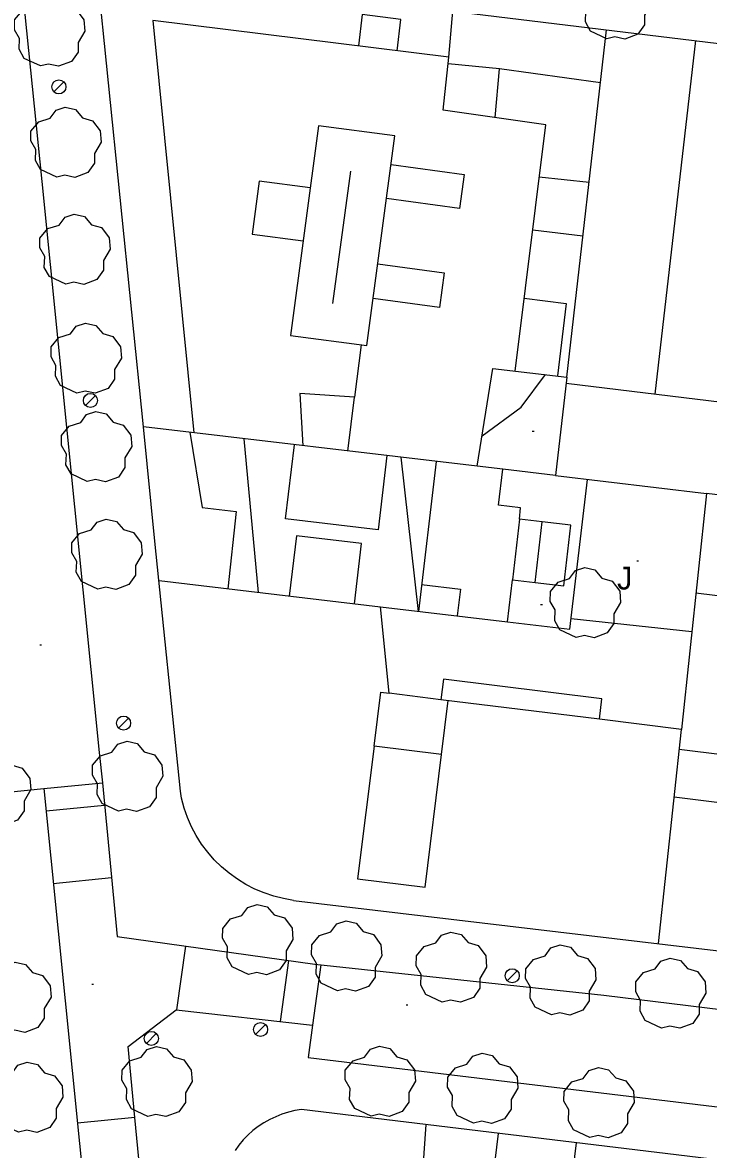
# Model space of a CAD drawing. Extents: x 431390 to 432653, y 4586754 to 4589600.
# Drawn here: x 431849.6 to 431888.6, y 4587029.7 to 4587093.8 of the extents above; entities that cross this region are included whole.
import ezdxf

# ---------------------------------------------------------------- set-up
doc = ezdxf.new("R2010")
doc.units = 0
for name, color, linetype in [('COM_17LS_LN', 7, 'Continuous'), ('COM_51_LN', 7, 'Continuous'), ('CON_01_LN', 7, 'Continuous'), ('CON_01FI_LN', 7, 'Continuous'), ('CON_03_LN', 7, 'Continuous'), ('CON_04_LN', 7, 'Continuous'), ('CON_07_LN', 7, 'Continuous'), ('CON_16_LN', 7, 'Continuous'), ('CON_29_LN', 7, 'Continuous'), ('ENE_06_PT', 7, 'Continuous'), ('ORO_03_PT', 7, 'Continuous'), ('TOP_15JA_TX', 7, 'Continuous'), ('VEG_03_PT', 7, 'Continuous'), ('VEG_06_LN', 7, 'Continuous')]:
    doc.layers.add(name, color=color, linetype=linetype)

msp = doc.modelspace()

# ---------------------------------------------------------------- linework, layer by layer
at = {"layer": 'COM_17LS_LN'}
for points in [[(431837.008, 4587166.5), (431842.053, 4587116.407), (431848.565, 4587051.747), (431848.738, 4587050.028), (431850.776, 4587050.233)], [(431849.159, 4587099.733), (431850.662, 4587084.802), (431853.937, 4587052.287), (431854.11, 4587050.568), (431854.957, 4587041.808), (431866.203, 4587040.244), (431882.634, 4587038.474), (431909.565, 4587035.179)], [(431850.776, 4587050.233), (431854.11, 4587050.568)], [(431850.776, 4587050.233), (431853.209, 4587026.07)], [(431866.538, 4587040.208), (431866.058, 4587036.756)], [(431855.957, 4587031.509), (431855.571, 4587035.553), (431858.31, 4587037.64), (431866.058, 4587036.756)], [(431866.058, 4587036.756), (431865.809, 4587034.924)], [(431865.809, 4587034.924), (431908.896, 4587029.72), (431931.717, 4587026.927), (431949.6, 4587024.752)], [(431860.702, 4586984.127), (431856.446, 4587026.396), (431855.957, 4587031.509)]]:
    msp.add_lwpolyline(points, dxfattribs=at)
at = {"layer": 'COM_51_LN'}
for points in [[(431854.236, 4587049.261), (431850.906, 4587048.94)], [(431851.32, 4587044.829), (431854.633, 4587045.163)], [(431858.841, 4587041.268), (431858.336, 4587037.637)], [(431864.702, 4587040.453), (431864.217, 4587036.966)], [(431855.957, 4587031.508), (431852.693, 4587031.193)]]:
    msp.add_lwpolyline(points, dxfattribs=at)
at = {"layer": 'CON_01_LN'}
for points in [[(431856.444, 4587070.829), (431853.79, 4587096.96), (431873.881, 4587094.519), (431904.331, 4587090.82)], [(431864.98, 4587043.87), (431864.415, 4587043.968), (431863.86, 4587044.108), (431863.316, 4587044.29), (431862.788, 4587044.513), (431862.278, 4587044.775), (431861.79, 4587045.075), (431861.325, 4587045.41), (431860.888, 4587045.78), (431860.479, 4587046.182), (431860.102, 4587046.614), (431859.759, 4587047.073), (431859.451, 4587047.556), (431859.181, 4587048.062), (431858.95, 4587048.586), (431858.759, 4587049.127), (431858.61, 4587049.68), (431858.55, 4587050.09), (431857.104, 4587064.328), (431856.444, 4587070.829)], [(431864.98, 4587043.87), (431902.943, 4587039.364), (431950.282, 4587033.571)], [(431903.511, 4587027.351), (431865.44, 4587031.96), (431865.064, 4587031.898), (431864.693, 4587031.809), (431864.329, 4587031.695), (431863.974, 4587031.555), (431863.63, 4587031.39), (431863.299, 4587031.202), (431862.981, 4587030.991), (431862.679, 4587030.759), (431862.394, 4587030.505), (431862.128, 4587030.232), (431861.881, 4587029.941), (431861.656, 4587029.634)]]:
    msp.add_lwpolyline(points, dxfattribs=at)
at = {"layer": 'CON_01FI_LN'}
msp.add_lwpolyline([(431873.372, 4587055.294), (431870.42, 4587055.66), (431869.927, 4587060.58), (431877.157, 4587059.724), (431877.44, 4587062.118), (431878.728, 4587061.966), (431879.137, 4587065.422), (431877.846, 4587065.575), (431877.891, 4587066.223), (431876.648, 4587066.37), (431876.889, 4587068.409), (431875.432, 4587068.581), (431876.33, 4587074.14), (431880.533, 4587073.662), (431879.893, 4587068.053), (431888.48, 4587067.037), (431887.048, 4587053.601), (431882.387, 4587054.178), (431882.531, 4587055.341), (431873.516, 4587056.457), (431873.372, 4587055.294)], dxfattribs=at)
at = {"layer": 'CON_03_LN'}
for points in [[(431880.533, 4587073.662), (431882.789, 4587093.437)], [(431875.432, 4587068.581), (431856.444, 4587070.829)], [(431896.142, 4587066.129), (431888.48, 4587067.037)], [(431857.333, 4587062.071), (431869.927, 4587060.58)], [(431885.748, 4587041.405), (431887.048, 4587053.601)]]:
    msp.add_lwpolyline(points, dxfattribs=at)
at = {"layer": 'CON_04_LN'}
for points in [[(431873.83, 4587091.87), (431874.052, 4587094.498)], [(431877.602, 4587073.995), (431879.33, 4587088.03), (431873.49, 4587088.85), (431873.83, 4587091.87), (431856.98, 4587093.97), (431859.306, 4587070.49)], [(431870.873, 4587092.239), (431871.095, 4587094.022), (431868.899, 4587094.296), (431868.677, 4587092.512)], [(431876.447, 4587088.435), (431876.7, 4587091.21), (431873.788, 4587091.499)], [(431882.444, 4587090.409), (431876.7, 4587091.21)], [(431869.15, 4587075.45), (431870.75, 4587087.39), (431866.413, 4587087.971), (431864.813, 4587076.031), (431869.15, 4587075.45)], [(431870.532, 4587085.76), (431874.692, 4587085.202), (431874.432, 4587083.265), (431870.272, 4587083.823)], [(431878.965, 4587085.067), (431881.799, 4587084.757)], [(431865.938, 4587084.426), (431863.028, 4587084.816), (431862.624, 4587081.799), (431865.534, 4587081.409)], [(431881.448, 4587081.68), (431878.591, 4587082.031)], [(431869.774, 4587080.107), (431873.56, 4587079.6), (431873.296, 4587077.627), (431869.51, 4587078.134)], [(431878.113, 4587078.145), (431880.503, 4587077.851), (431879.995, 4587073.723)], [(431868.079, 4587069.452), (431868.46, 4587072.52), (431865.34, 4587072.72), (431865.518, 4587069.755)], [(431901.2, 4587070.77), (431880.492, 4587073.299)], [(431859.092, 4587070.516), (431859.78, 4587066.24), (431861.73, 4587066), (431861.243, 4587061.608)], [(431862.156, 4587070.153), (431862.971, 4587061.404)], [(431870.301, 4587069.188), (431869.8, 4587064.96), (431864.534, 4587065.583), (431865.035, 4587069.812)], [(431873.097, 4587068.857), (431872.086, 4587060.324), (431871.101, 4587069.094)], [(431877.846, 4587065.575), (431877.44, 4587062.118)], [(431868.448, 4587060.755), (431868.855, 4587064.192), (431865.15, 4587064.631), (431864.743, 4587061.194)], [(431872.266, 4587061.844), (431874.477, 4587061.582), (431874.297, 4587060.063)], [(431895.447, 4587060.426), (431887.874, 4587061.349)], [(431869.573, 4587052.646), (431869.956, 4587055.718), (431870.42, 4587055.66)], [(431882.387, 4587054.178), (431873.372, 4587055.294)], [(431873.406, 4587052.169), (431873.788, 4587055.243)], [(431872.468, 4587044.619), (431873.406, 4587052.169), (431869.573, 4587052.646), (431868.634, 4587045.096), (431872.468, 4587044.619)], [(431886.928, 4587052.471), (431891.972, 4587051.856), (431891.639, 4587049.126), (431886.636, 4587049.736)], [(431871.676, 4587018.848), (431872.526, 4587031.102)], [(431881.065, 4587030.068), (431880.688, 4587026.952), (431876.266, 4587027.487), (431876.643, 4587030.604)]]:
    msp.add_lwpolyline(points, dxfattribs=at)
at = {"layer": 'CON_07_LN'}
for points in [[(431875.711, 4587070.309), (431877.94, 4587071.95), (431879.327, 4587073.799)], [(431878.728, 4587061.966), (431880.358, 4587061.773), (431880.767, 4587065.229), (431879.137, 4587065.422)]]:
    msp.add_lwpolyline(points, dxfattribs=at)
at = {"layer": 'CON_16_LN'}
for points in [[(431879.893, 4587068.053), (431876.889, 4587068.409)], [(431877.157, 4587059.724), (431880.708, 4587059.304), (431881.718, 4587067.837)]]:
    msp.add_lwpolyline(points, dxfattribs=at)
at = {"layer": 'CON_29_LN'}
for points in [[(431887.858, 4587092.821), (431885.536, 4587072.683)], [(431868.221, 4587085.388), (431867.212, 4587077.858)], [(431868.837, 4587075.492), (431868.46, 4587072.52)]]:
    msp.add_lwpolyline(points, dxfattribs=at)
at = {"layer": 'ENE_06_PT'}
for p, q in [((431851.922, 4587090.462), (431851.356, 4587089.896)), ((431853.712, 4587072.612), (431853.146, 4587072.046)), ((431855.602, 4587054.242), (431855.036, 4587053.676)), ((431877.712, 4587039.862), (431877.146, 4587039.296)), ((431863.392, 4587036.802), (431862.826, 4587036.236)), ((431857.179, 4587036.29), (431856.613, 4587035.724))]:
    msp.add_line(p, q, dxfattribs=at)
for centre in [(431851.639, 4587090.179), (431853.429, 4587072.329), (431855.319, 4587053.959), (431877.429, 4587039.579), (431863.109, 4587036.519), (431856.896, 4587036.007)]:
    msp.add_circle(centre, 0.4, dxfattribs=at)
at = {"layer": 'ORO_03_PT'}
for p, q in [((431878.57, 4587070.58), (431878.67, 4587070.58)), ((431884.51, 4587063.19), (431884.61, 4587063.19)), ((431879.04, 4587060.72), (431879.14, 4587060.72)), ((431850.556, 4587058.424), (431850.656, 4587058.424)), ((431853.511, 4587039.094), (431853.611, 4587039.094)), ((431871.388, 4587037.92), (431871.488, 4587037.92))]:
    msp.add_line(p, q, dxfattribs=at)
at = {"layer": 'VEG_03_PT'}
for points in [[(431882.804, 4587092.921), (431881.877, 4587093.356), (431881.589, 4587093.877), (431881.612, 4587094.491), (431881.33, 4587094.983), (431881.338, 4587095.546), (431881.779, 4587096.081), (431882.432, 4587096.285), (431882.767, 4587096.736), (431883.293, 4587096.906), (431883.873, 4587096.773), (431884.273, 4587096.307), (431884.847, 4587096.137), (431885.281, 4587095.554), (431885.33, 4587094.912), (431884.947, 4587094.265), (431884.947, 4587093.715), (431884.575, 4587093.181), (431883.836, 4587092.906), (431883.271, 4587093.034), (431882.804, 4587092.921)], [(431850.584, 4587091.371), (431849.657, 4587091.806), (431849.369, 4587092.327), (431849.392, 4587092.941), (431849.11, 4587093.433), (431849.118, 4587093.996), (431849.559, 4587094.531), (431850.212, 4587094.735), (431850.547, 4587095.186), (431851.073, 4587095.356), (431851.653, 4587095.223), (431852.053, 4587094.757), (431852.627, 4587094.587), (431853.061, 4587094.004), (431853.11, 4587093.362), (431852.727, 4587092.715), (431852.727, 4587092.165), (431852.355, 4587091.631), (431851.616, 4587091.356), (431851.051, 4587091.484), (431850.584, 4587091.371)], [(431851.514, 4587085.041), (431850.587, 4587085.476), (431850.299, 4587085.997), (431850.322, 4587086.611), (431850.04, 4587087.103), (431850.048, 4587087.666), (431850.489, 4587088.201), (431851.142, 4587088.405), (431851.477, 4587088.856), (431852.003, 4587089.026), (431852.583, 4587088.893), (431852.983, 4587088.427), (431853.557, 4587088.257), (431853.991, 4587087.674), (431854.04, 4587087.032), (431853.657, 4587086.385), (431853.657, 4587085.835), (431853.285, 4587085.301), (431852.546, 4587085.026), (431851.981, 4587085.154), (431851.514, 4587085.041)], [(431852.024, 4587078.951), (431851.097, 4587079.386), (431850.809, 4587079.907), (431850.832, 4587080.521), (431850.55, 4587081.013), (431850.558, 4587081.576), (431850.999, 4587082.111), (431851.652, 4587082.315), (431851.987, 4587082.766), (431852.513, 4587082.936), (431853.093, 4587082.803), (431853.493, 4587082.337), (431854.067, 4587082.167), (431854.501, 4587081.584), (431854.55, 4587080.942), (431854.167, 4587080.295), (431854.167, 4587079.745), (431853.795, 4587079.211), (431853.056, 4587078.936), (431852.491, 4587079.064), (431852.024, 4587078.951)], [(431852.664, 4587072.751), (431851.737, 4587073.186), (431851.449, 4587073.707), (431851.472, 4587074.321), (431851.19, 4587074.813), (431851.198, 4587075.376), (431851.639, 4587075.911), (431852.292, 4587076.115), (431852.627, 4587076.566), (431853.153, 4587076.736), (431853.733, 4587076.603), (431854.133, 4587076.137), (431854.707, 4587075.967), (431855.141, 4587075.384), (431855.19, 4587074.742), (431854.807, 4587074.095), (431854.807, 4587073.545), (431854.435, 4587073.011), (431853.696, 4587072.736), (431853.131, 4587072.864), (431852.664, 4587072.751)], [(431853.254, 4587067.711), (431852.327, 4587068.146), (431852.039, 4587068.667), (431852.062, 4587069.281), (431851.78, 4587069.773), (431851.788, 4587070.336), (431852.229, 4587070.871), (431852.882, 4587071.075), (431853.217, 4587071.526), (431853.743, 4587071.696), (431854.323, 4587071.563), (431854.723, 4587071.097), (431855.297, 4587070.927), (431855.731, 4587070.344), (431855.78, 4587069.702), (431855.397, 4587069.055), (431855.397, 4587068.505), (431855.025, 4587067.971), (431854.286, 4587067.696), (431853.721, 4587067.824), (431853.254, 4587067.711)], [(431853.844, 4587061.591), (431852.917, 4587062.026), (431852.629, 4587062.547), (431852.652, 4587063.161), (431852.37, 4587063.653), (431852.378, 4587064.216), (431852.819, 4587064.751), (431853.472, 4587064.955), (431853.807, 4587065.406), (431854.333, 4587065.576), (431854.913, 4587065.443), (431855.313, 4587064.977), (431855.887, 4587064.807), (431856.321, 4587064.224), (431856.37, 4587063.582), (431855.987, 4587062.935), (431855.987, 4587062.385), (431855.615, 4587061.851), (431854.876, 4587061.576), (431854.311, 4587061.704), (431853.844, 4587061.591)], [(431881.064, 4587058.831), (431880.137, 4587059.266), (431879.849, 4587059.787), (431879.872, 4587060.401), (431879.59, 4587060.893), (431879.598, 4587061.456), (431880.039, 4587061.991), (431880.692, 4587062.195), (431881.027, 4587062.646), (431881.553, 4587062.816), (431882.133, 4587062.683), (431882.533, 4587062.217), (431883.107, 4587062.047), (431883.541, 4587061.464), (431883.59, 4587060.822), (431883.207, 4587060.175), (431883.207, 4587059.625), (431882.835, 4587059.091), (431882.096, 4587058.816), (431881.531, 4587058.944), (431881.064, 4587058.831)], [(431855.024, 4587048.941), (431854.097, 4587049.376), (431853.809, 4587049.897), (431853.832, 4587050.511), (431853.55, 4587051.003), (431853.558, 4587051.566), (431853.999, 4587052.101), (431854.652, 4587052.305), (431854.987, 4587052.756), (431855.513, 4587052.926), (431856.093, 4587052.793), (431856.493, 4587052.327), (431857.067, 4587052.157), (431857.501, 4587051.574), (431857.55, 4587050.932), (431857.167, 4587050.285), (431857.167, 4587049.735), (431856.795, 4587049.201), (431856.056, 4587048.926), (431855.491, 4587049.054), (431855.024, 4587048.941)], [(431847.514, 4587048.181), (431846.587, 4587048.616), (431846.299, 4587049.137), (431846.322, 4587049.751), (431846.04, 4587050.243), (431846.048, 4587050.806), (431846.489, 4587051.341), (431847.142, 4587051.545), (431847.477, 4587051.996), (431848.003, 4587052.166), (431848.583, 4587052.033), (431848.983, 4587051.567), (431849.557, 4587051.397), (431849.991, 4587050.814), (431850.04, 4587050.172), (431849.657, 4587049.525), (431849.657, 4587048.975), (431849.285, 4587048.441), (431848.546, 4587048.166), (431847.981, 4587048.294), (431847.514, 4587048.181)], [(431862.424, 4587039.651), (431861.497, 4587040.086), (431861.209, 4587040.607), (431861.232, 4587041.221), (431860.95, 4587041.713), (431860.958, 4587042.276), (431861.399, 4587042.811), (431862.052, 4587043.015), (431862.387, 4587043.466), (431862.913, 4587043.636), (431863.493, 4587043.503), (431863.893, 4587043.037), (431864.467, 4587042.867), (431864.901, 4587042.284), (431864.95, 4587041.642), (431864.567, 4587040.995), (431864.567, 4587040.445), (431864.195, 4587039.911), (431863.456, 4587039.636), (431862.891, 4587039.764), (431862.424, 4587039.651)], [(431867.484, 4587038.711), (431866.557, 4587039.146), (431866.269, 4587039.667), (431866.292, 4587040.281), (431866.01, 4587040.773), (431866.018, 4587041.336), (431866.459, 4587041.871), (431867.112, 4587042.075), (431867.447, 4587042.526), (431867.973, 4587042.696), (431868.553, 4587042.563), (431868.953, 4587042.097), (431869.527, 4587041.927), (431869.961, 4587041.344), (431870.01, 4587040.702), (431869.627, 4587040.055), (431869.627, 4587039.505), (431869.255, 4587038.971), (431868.516, 4587038.696), (431867.951, 4587038.824), (431867.484, 4587038.711)], [(431873.444, 4587038.081), (431872.517, 4587038.516), (431872.229, 4587039.037), (431872.252, 4587039.651), (431871.97, 4587040.143), (431871.978, 4587040.706), (431872.419, 4587041.241), (431873.072, 4587041.445), (431873.407, 4587041.896), (431873.933, 4587042.066), (431874.513, 4587041.933), (431874.913, 4587041.467), (431875.487, 4587041.297), (431875.921, 4587040.714), (431875.97, 4587040.072), (431875.587, 4587039.425), (431875.587, 4587038.875), (431875.215, 4587038.341), (431874.476, 4587038.066), (431873.911, 4587038.194), (431873.444, 4587038.081)], [(431879.664, 4587037.351), (431878.737, 4587037.786), (431878.449, 4587038.307), (431878.472, 4587038.921), (431878.19, 4587039.413), (431878.198, 4587039.976), (431878.639, 4587040.511), (431879.292, 4587040.715), (431879.627, 4587041.166), (431880.153, 4587041.336), (431880.733, 4587041.203), (431881.133, 4587040.737), (431881.707, 4587040.567), (431882.141, 4587039.984), (431882.19, 4587039.342), (431881.807, 4587038.695), (431881.807, 4587038.145), (431881.435, 4587037.611), (431880.696, 4587037.336), (431880.131, 4587037.464), (431879.664, 4587037.351)], [(431848.664, 4587036.371), (431847.737, 4587036.806), (431847.449, 4587037.327), (431847.472, 4587037.941), (431847.19, 4587038.433), (431847.198, 4587038.996), (431847.639, 4587039.531), (431848.292, 4587039.735), (431848.627, 4587040.186), (431849.153, 4587040.356), (431849.733, 4587040.223), (431850.133, 4587039.757), (431850.707, 4587039.587), (431851.141, 4587039.004), (431851.19, 4587038.362), (431850.807, 4587037.715), (431850.807, 4587037.165), (431850.435, 4587036.631), (431849.696, 4587036.356), (431849.131, 4587036.484), (431848.664, 4587036.371)], [(431885.924, 4587036.601), (431884.997, 4587037.036), (431884.709, 4587037.557), (431884.732, 4587038.171), (431884.45, 4587038.663), (431884.458, 4587039.226), (431884.899, 4587039.761), (431885.552, 4587039.965), (431885.887, 4587040.416), (431886.413, 4587040.586), (431886.993, 4587040.453), (431887.393, 4587039.987), (431887.967, 4587039.817), (431888.401, 4587039.234), (431888.45, 4587038.592), (431888.067, 4587037.945), (431888.067, 4587037.395), (431887.695, 4587036.861), (431886.956, 4587036.586), (431886.391, 4587036.714), (431885.924, 4587036.601)], [(431856.694, 4587031.571), (431855.767, 4587032.006), (431855.479, 4587032.527), (431855.502, 4587033.141), (431855.22, 4587033.633), (431855.228, 4587034.196), (431855.669, 4587034.731), (431856.322, 4587034.935), (431856.657, 4587035.386), (431857.183, 4587035.556), (431857.763, 4587035.423), (431858.163, 4587034.957), (431858.737, 4587034.787), (431859.171, 4587034.204), (431859.22, 4587033.562), (431858.837, 4587032.915), (431858.837, 4587032.365), (431858.465, 4587031.831), (431857.726, 4587031.556), (431857.161, 4587031.684), (431856.694, 4587031.571)], [(431869.394, 4587031.581), (431868.467, 4587032.016), (431868.179, 4587032.537), (431868.202, 4587033.151), (431867.92, 4587033.643), (431867.928, 4587034.206), (431868.369, 4587034.741), (431869.022, 4587034.945), (431869.357, 4587035.396), (431869.883, 4587035.566), (431870.463, 4587035.433), (431870.863, 4587034.967), (431871.437, 4587034.797), (431871.871, 4587034.214), (431871.92, 4587033.572), (431871.537, 4587032.925), (431871.537, 4587032.375), (431871.165, 4587031.841), (431870.426, 4587031.566), (431869.861, 4587031.694), (431869.394, 4587031.581)], [(431875.224, 4587031.181), (431874.297, 4587031.616), (431874.009, 4587032.137), (431874.032, 4587032.751), (431873.75, 4587033.243), (431873.758, 4587033.806), (431874.199, 4587034.341), (431874.852, 4587034.545), (431875.187, 4587034.996), (431875.713, 4587035.166), (431876.293, 4587035.033), (431876.693, 4587034.567), (431877.267, 4587034.397), (431877.701, 4587033.814), (431877.75, 4587033.172), (431877.367, 4587032.525), (431877.367, 4587031.975), (431876.995, 4587031.441), (431876.256, 4587031.166), (431875.691, 4587031.294), (431875.224, 4587031.181)], [(431849.344, 4587030.671), (431848.417, 4587031.106), (431848.129, 4587031.627), (431848.152, 4587032.241), (431847.87, 4587032.733), (431847.878, 4587033.296), (431848.319, 4587033.831), (431848.972, 4587034.035), (431849.307, 4587034.486), (431849.833, 4587034.656), (431850.413, 4587034.523), (431850.813, 4587034.057), (431851.387, 4587033.887), (431851.821, 4587033.304), (431851.87, 4587032.662), (431851.487, 4587032.015), (431851.487, 4587031.465), (431851.115, 4587030.931), (431850.376, 4587030.656), (431849.811, 4587030.784), (431849.344, 4587030.671)], [(431881.844, 4587030.371), (431880.917, 4587030.806), (431880.629, 4587031.327), (431880.652, 4587031.941), (431880.37, 4587032.433), (431880.378, 4587032.996), (431880.819, 4587033.531), (431881.472, 4587033.735), (431881.807, 4587034.186), (431882.333, 4587034.356), (431882.913, 4587034.223), (431883.313, 4587033.757), (431883.887, 4587033.587), (431884.321, 4587033.004), (431884.37, 4587032.362), (431883.987, 4587031.715), (431883.987, 4587031.165), (431883.615, 4587030.631), (431882.876, 4587030.356), (431882.311, 4587030.484), (431881.844, 4587030.371)]]:
    msp.add_lwpolyline(points, dxfattribs=at)
at = {"layer": 'VEG_06_LN'}
msp.add_lwpolyline([(431887.641, 4587059.163), (431880.778, 4587059.894)], dxfattribs=at)

# ---------------------------------------------------------------- texts
at = {"layer": 'TOP_15JA_TX'}
msp.add_text('J', height=1.3, dxfattribs=at).set_placement((431883.39, 4587061.565))

doc.saveas('drawing.dxf')
